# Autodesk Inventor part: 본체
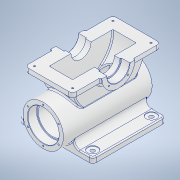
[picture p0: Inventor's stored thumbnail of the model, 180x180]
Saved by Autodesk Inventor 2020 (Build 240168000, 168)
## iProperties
Created: 2023-07
Part Number: 본체
Material: 알루미늄 6061
Document SubType Name: Modeling
Designer: oem
Density: 2.7 g/cm^3
Appearance: 알루미늄 - 평지
Mass: 5723.66 g
Surface Area: 2848.24 cm^2
Volume: 2119.87 cm^3
Author: oem
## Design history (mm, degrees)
sketch "스케치1"
  geometry: C1 r 55 at (0, 0); 1 further point
  constraints: 1 centre point, 1 coincident
  dimensions: "d0" = 110 diameter of C1
extrude "돌출1" new body sketch "스케치1" distance "d1" = 242; taper "d2" = 0 deg
sketch "스케치2"
  geometry: C1 r 55 at (0, 0) reference; C2 r 42.5 at (0, 0)
  constraints: 1 centre point, 1 coincident
  dimensions: "d3" = 85 diameter of C2
extrude "돌출2" cut sketch "스케치2" distance "d4" = 25; taper "d5" = 0 deg
sketch "스케치3" dims "d6" = 97
  geometry: L1 (0, 0)-(0, 48.5); C1 r 55 at (0, 0) reference; 1 further point
  constraints: 2 coincident, 2 end point, 1 vertical, 1 vertical alignment, 2 other
hole "구멍1" sketch "스케치3" at (0, 48.5) diameter "d7" = 4.134; stored, may be unused: countersink angle "d11" = 90 deg, drill point angle "d13" = 118 deg; dims "d8" = 10, "d9" = 4, "d10" = 2, "d12" = 12
sketch "스케치4"
  geometry: C1 r 42.5 at (0, 0) reference; C2 r 38.5 at (0, 0)
  constraints: 1 centre point, 1 coincident
  dimensions: "d17" = 77 diameter of C2
extrude "돌출3" cut sketch "스케치4" extent not by distance; stored distance "d18" = 25; taper "d19" = 0 deg
fillet "모깎기1" dims "d20" = 1.1
node "작업 평면1"
sketch "스케치5"
  geometry: L1 (0, 0)-(0, -60); C1 r 2.067 at (-42.002, 24.25) reference; C2 r 2.067 at (-42.002, -24.25) reference; C3 r 2.067 at (0, -48.5) reference; C4 r 2.067 at (42.002, -24.25) reference; C5 r 2.067 at (42.002, 24.25) reference; C6 r 2.067 at (0, 48.5) reference; C7 r 42.5 at (0, 0) reference; C8 r 55 at (0, 0) reference; C9 r 41.4 at (0, 0) reference
  constraints: 2 end point, 1 vertical
  dimensions: "d22" = 60 distance of L1.start L1.end
node "작업 평면3"
sketch "스케치6"
  geometry: L1 (-42.5, 0)-(42.5, 0) reference; L2 (0, 0)-(100, 0); L3 (0, 0)-(-100, 0); L4 (100, 0)-(100, -35); L5 (100, -35)-(100, -235); L6 (100, -35)-(-100, -35); L7 (-100, -35)-(-100, -235); L8 (-100, -235)-(100, -235); L9 (100, -235)-(100, -35); 2 further points
  constraints: 16 end point, 3 horizontal, 2 parallel, 1 midpoint, 1 perpendicular, 1 vertical
  dimensions: "d24" = 100 distance of L2.start L2.end; "d25" = 100 distance of L2.start L3.end; "d26" = 35 distance of L2.end L4.end; "d29" = 200 distance of L6.end L7.end; "d30" = 200 distance between parallel lines of L5 L7
extrude "돌출4" join sketch "스케치6" distance "d27" = 15; taper "d28" = 0 deg
sketch "스케치8"
  geometry: L1 (100, 35)-(-100, 35) reference; L2 (-100, 35)-(-100, 235) reference; L3 (-100, 235)-(100, 235) reference; L4 (100, 235)-(100, 35) reference; L5 (80, 215)-(-80, 215); L6 (-80, 215)-(-80, 55); L7 (-80, 55)-(80, 55); L8 (80, 55)-(80, 215); L9 (80, 215)-(-80, 55); L10 (-80, 215)-(80, 55); 6 further points
  constraints: 12 end point, 4 coincident, 2 midpoint, 2 parallel, 1 horizontal, 1 perpendicular
  dimensions: "d31" = 160 distance of L7.end L6.end; "d32" = 160 distance of L6.end L5.end; "d33" = 20 distance between parallel lines of L4 L8; "d34" = 20 distance between parallel lines of L1 L7
hole "구멍2" sketch "스케치8" at (-80, 55), (-80, 215), (80, 215), (80, 55) diameter "d35" = 11; stored, may be unused: countersink angle "d39" = 90 deg, drill point angle "d41" = 118 deg; dims "d36" = 10, "d37" = 28, "d38" = 2, "d40" = 15
sketch "스케치9"
  geometry: L1 (0, 15)-(68.377, 15) reference; L2 (0, 0)-(0, 15) reference; L3 (200, 0)-(0, 0) reference; L4 (200, 0)-(200, 15) reference; L5 (131.623, 15)-(200, 15) reference; A1 r 55 centre (100, 60) between (68.377, 15) and (131.623, 15) reference
fillet "모깎기2" dims "d42" = 15
sketch "스케치10"
  geometry: C1 r 2.067 at (-42.002, 24.25) reference; C2 r 2.067 at (-42.002, -24.25) reference; C3 r 2.067 at (0, -48.5) reference; C4 r 2.067 at (42.002, -24.25) reference; C5 r 2.067 at (42.002, 24.25) reference; C6 r 2.067 at (0, 48.5) reference; C7 r 42.5 at (0, 0) reference; C8 r 55 at (0, 0) reference
sketch "스케치11"
  geometry: L1 (-100, -60)-(100, -60) reference; L2 (0, -60)-(0, 100); C1 r 42.5 at (0, 0) reference; C2 r 55 at (0, 0) reference; C3 r 38.5 at (0, 0)
  constraints: 2 end point, 1 centre point, 1 coincident, 1 midpoint, 1 vertical
  dimensions: "d43" = 160 distance of L2.start L2.end
node "작업 평면4"
sketch "스케치12"
  geometry: L1 (0, -242)-(0, -135); L2 (65, -255)-(-65, -255); L3 (-65, -255)-(-65, -15); L4 (-65, -15)-(65, -15); L5 (65, -15)-(65, -255); L6 (65, -255)-(-65, -15); L7 (-65, -255)-(65, -15)
  constraints: 14 end point, 2 midpoint, 2 parallel, 1 horizontal, 1 perpendicular, 1 vertical
  dimensions: "d44" = 107 distance of L1.start L1.end; "d45" = 130 distance of L3.end L4.end; "d46" = 240 distance of L2.end L3.end
extrude "돌출5" join sketch "스케치12" distance "d47" = 15; taper "d48" = 0 deg
node "작업 평면5"
sketch "스케치13"
  geometry: L1 (13, -155)-(13, -45) reference; L2 (13, -45)-(120, -45); L3 (13, -45)-(255, -45) reference; L4 (120, -45)-(120, 0); L5 (0, 0)-(240, 0) reference; L6 (240, -15)-(0, -15) reference; L7 (34.303, -15)-(205.697, -15); A1 r 100 centre (120, 0) between (20, 0) and (220, 0); A2 r 87 centre (120, 0) between (34.303, -15) and (205.697, -15); 3 further points
  constraints: 6 end point, 5 point on line, 4 point on circle, 2 centre point, 2 coincident, 1 midpoint
  dimensions: "d49" = 107 distance of L1.end L2.end; "d50" = 200 diameter of A1; "d51" = 174 diameter of A2
extrude "돌출6" join sketch "스케치13" stored distance "d52" = 90; taper "d53" = 0 deg
sketch "스케치15"
  geometry: L1 (65, 107.5)-(-65, 107.5) reference; L2 (32, 107.5)-(32, 48) reference; L3 (32, 48)-(-32, 48) reference; L4 (-32, 48)-(-32, 107.5) reference; L5 (65, 107.5)-(-65, 107.5) reference; L6 (-65, 255)-(-65, 15) reference; L7 (-65, 15)-(65, 15) reference; L8 (65, 15)-(65, 255) reference; 4 further points
sketch "스케치16"
  geometry: L1 (0, 0)-(240, 0) reference; C1 r 45 at (120, 0); 3 further points
  constraints: 1 centre point, 1 midpoint
  dimensions: "d59" = 90 diameter of C1
extrude "돌출9" join sketch "스케치16" stored distance "d60" = 140; taper "d61" = 0 deg
sketch "스케치17"
  geometry: L1 (165, 0)-(75, 0) reference; C1 r 31 at (120, 0); A1 r 45 centre (120, 0) between (75, 0) and (165, 0) reference; 3 further points
  constraints: 1 centre point, 1 coincident
  dimensions: "d62" = 62 diameter of C1
extrude "돌출10" cut sketch "스케치17" distance "d63" = 23; taper "d64" = 0 deg
fillet "모깎기3" dims "d65" = 1
sketch "스케치18"
  geometry: L1 (90, 0)-(150, 0) reference; C1 r 27.5 at (120, 0); A1 r 30 centre (120, 0) between (90, 0) and (150, 0) reference; 3 further points
  constraints: 1 centre point, 1 coincident
  dimensions: "d66" = 55 diameter of C1
extrude "돌출11" cut sketch "스케치18" extent not by distance; stored distance "d67" = 23; taper "d68" = 0 deg
extrude "돌출12" cut sketch "스케치13" stored distance "d69" = 64; taper "d70" = 0 deg
extrude "돌출13" cut sketch "스케치11" extent not by distance; stored distance "d71" = 0; taper "d72" = 0 deg
sketch "스케치19" dims "d73" = 74
  geometry: L1 (-120, 0)-(-146.163, -26.163); L2 (0, 0)-(-240, 0) reference; L3 (-120, -45)-(-120, 0) reference; L4 (-120, 0)-(-93.837, -26.163); A1 r 45 centre (-120, 0) between (-165, 0) and (-75, 0) reference; 3 further points
  constraints: 4 end point, 3 coincident, 1 symmetric about line, 3 other
  dimensions: "d74" = 45 deg angle of L3 L1
hole "구멍3" sketch "스케치19" at (-93.837, -26.163), (-146.163, -26.163) diameter "d75" = 4.134; stored, may be unused: countersink angle "d79" = 90 deg, drill point angle "d81" = 118 deg; dims "d76" = 10, "d77" = 28, "d78" = 2, "d80" = 12
sketch "스케치20"
  geometry: L1 (49.693, 235)-(-49.693, 235) reference; L2 (65, 180)-(65, 255) reference; L3 (-32, 162.5)-(-32, 222) reference; L4 (-32, 222)-(32, 222) reference; L5 (32, 222)-(32, 162.5) reference; L6 (32, 162.5)-(47, 162.5) reference; L7 (47, 162.5)-(47, 165) reference; L8 (48, 166)-(70, 166) reference; L9 (70, 180)-(70, 166) reference; L10 (70, 180)-(65, 180) reference; L11 (65, 180)-(65, 255) reference; L12 (65, 255)-(-65, 255) reference; L13 (-65, 255)-(-65, 180) reference; L14 (-65, 180)-(-70, 180) reference; L15 (-70, 166)-(-70, 180) reference; L16 (-70, 166)-(-48, 166) reference; L17 (-47, 165)-(-47, 162.5) reference; L18 (-47, 162.5)-(-32, 162.5) reference; L19 (65, 15)-(-65, 15) reference; L20 (0, 15)-(0, 135); L21 (-65, 255)-(65, 255) reference; L22 (52, 242)-(-52, 242); L23 (-52, 242)-(-52, 28); L24 (-52, 28)-(52, 28); L25 (52, 28)-(52, 242); L26 (52, 242)-(-52, 28); L27 (-52, 242)-(52, 28); A1 r 1 centre (48, 165) between (48, 166) and (47, 165) reference; A2 r 1 centre (-48, 165) between (-47, 165) and (-48, 166) reference; 5 further points
  constraints: 14 end point, 4 coincident, 3 midpoint, 2 parallel, 2 perpendicular, 1 horizontal
  dimensions: "d82" = 120 distance of L20.start L20.end; "d83" = 104 distance of L24.end L23.end; "d84" = 214 distance of L23.end L22.end
hole "구멍4" sketch "스케치20" at (-52, 242), (52, 242), (52, 28), (-52, 28) diameter "d85" = 4.917; stored, may be unused: countersink angle "d89" = 90 deg, drill point angle "d91" = 118 deg; dims "d86" = 18, "d87" = 28, "d88" = 2, "d90" = 20
fillet "모깎기4" dims "d92" = 3
fillet "모깎기5" dims "d93" = 10
fillet "모깎기6" dims "d94" = 3
chamfer "모따기1" distance "d95" = 1; stored, may be unused: second distance "d96" = 2, angle "d97" = 45 deg
fillet "모깎기7" dims "d98" = 3
fillet "모깎기8" dims "d99" = 10
node "작업 평면6"
sketch "스케치21"
  geometry: C1 r 42.5 at (0, 0); C2 r 38.5 at (0, 0); 1 further point
  constraints: 2 centre point, 2 coincident
  dimensions: "d101" = 77 diameter of C2
chamfer "모따기2" distance "d102" = 1; stored, may be unused: second distance "d103" = 2, angle "d104" = 45 deg
sketch "스케치22"
  geometry: L1 (43.5, 242)-(-43.5, 242) reference; 1 further point
fillet "모깎기9" dims "d105" = 3
sketch "스케치23"
  geometry: L1 (-69, 104)-(-69, 166) reference; L2 (-69, 135)-(-100, 135); L3 (-100, 45)-(-100, 225) reference; L4 (-100, 135)-(-85, 135); 2 further points
  constraints: 4 end point, 2 midpoint, 1 coincident, 1 point on line, 1 other
  dimensions: "d106" = 15 distance of L2.end L4.end
feature "엠보싱1" sketch "스케치23" dims "d107" = 0.5, "d108" = 0
fillet "모깎기10" dims "d109" = 3
node "솔리드1"
pattern_circular "원형 패턴1" dims angle "d15" = 360 deg
mirror "미러1"
mirror "미러2"
mirror "미러3"
node "투영된 루프2"
node "투영된 루프3"
feature "A9D066F2-1C7D-4E18-AEED-F7BC21143FA4" dims "d35" = 11, "d36" = 10, "d37" = 28, "d38" = 2, "d39" = 90 deg, "d40" = 15, "d41" = 118 deg
other parameters: "d21" = -121, "d100" = -25
